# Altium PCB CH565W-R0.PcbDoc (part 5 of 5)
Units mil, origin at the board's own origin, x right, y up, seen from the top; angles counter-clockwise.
Board outline 3947.04 x 3947.04 mil, 4 copper layers (Top Layer, Layer 1, Layer 2, Bottom Layer), stack 23.756 mil thick; 204 components, 168 nets, 932 pads, 1005 vias.
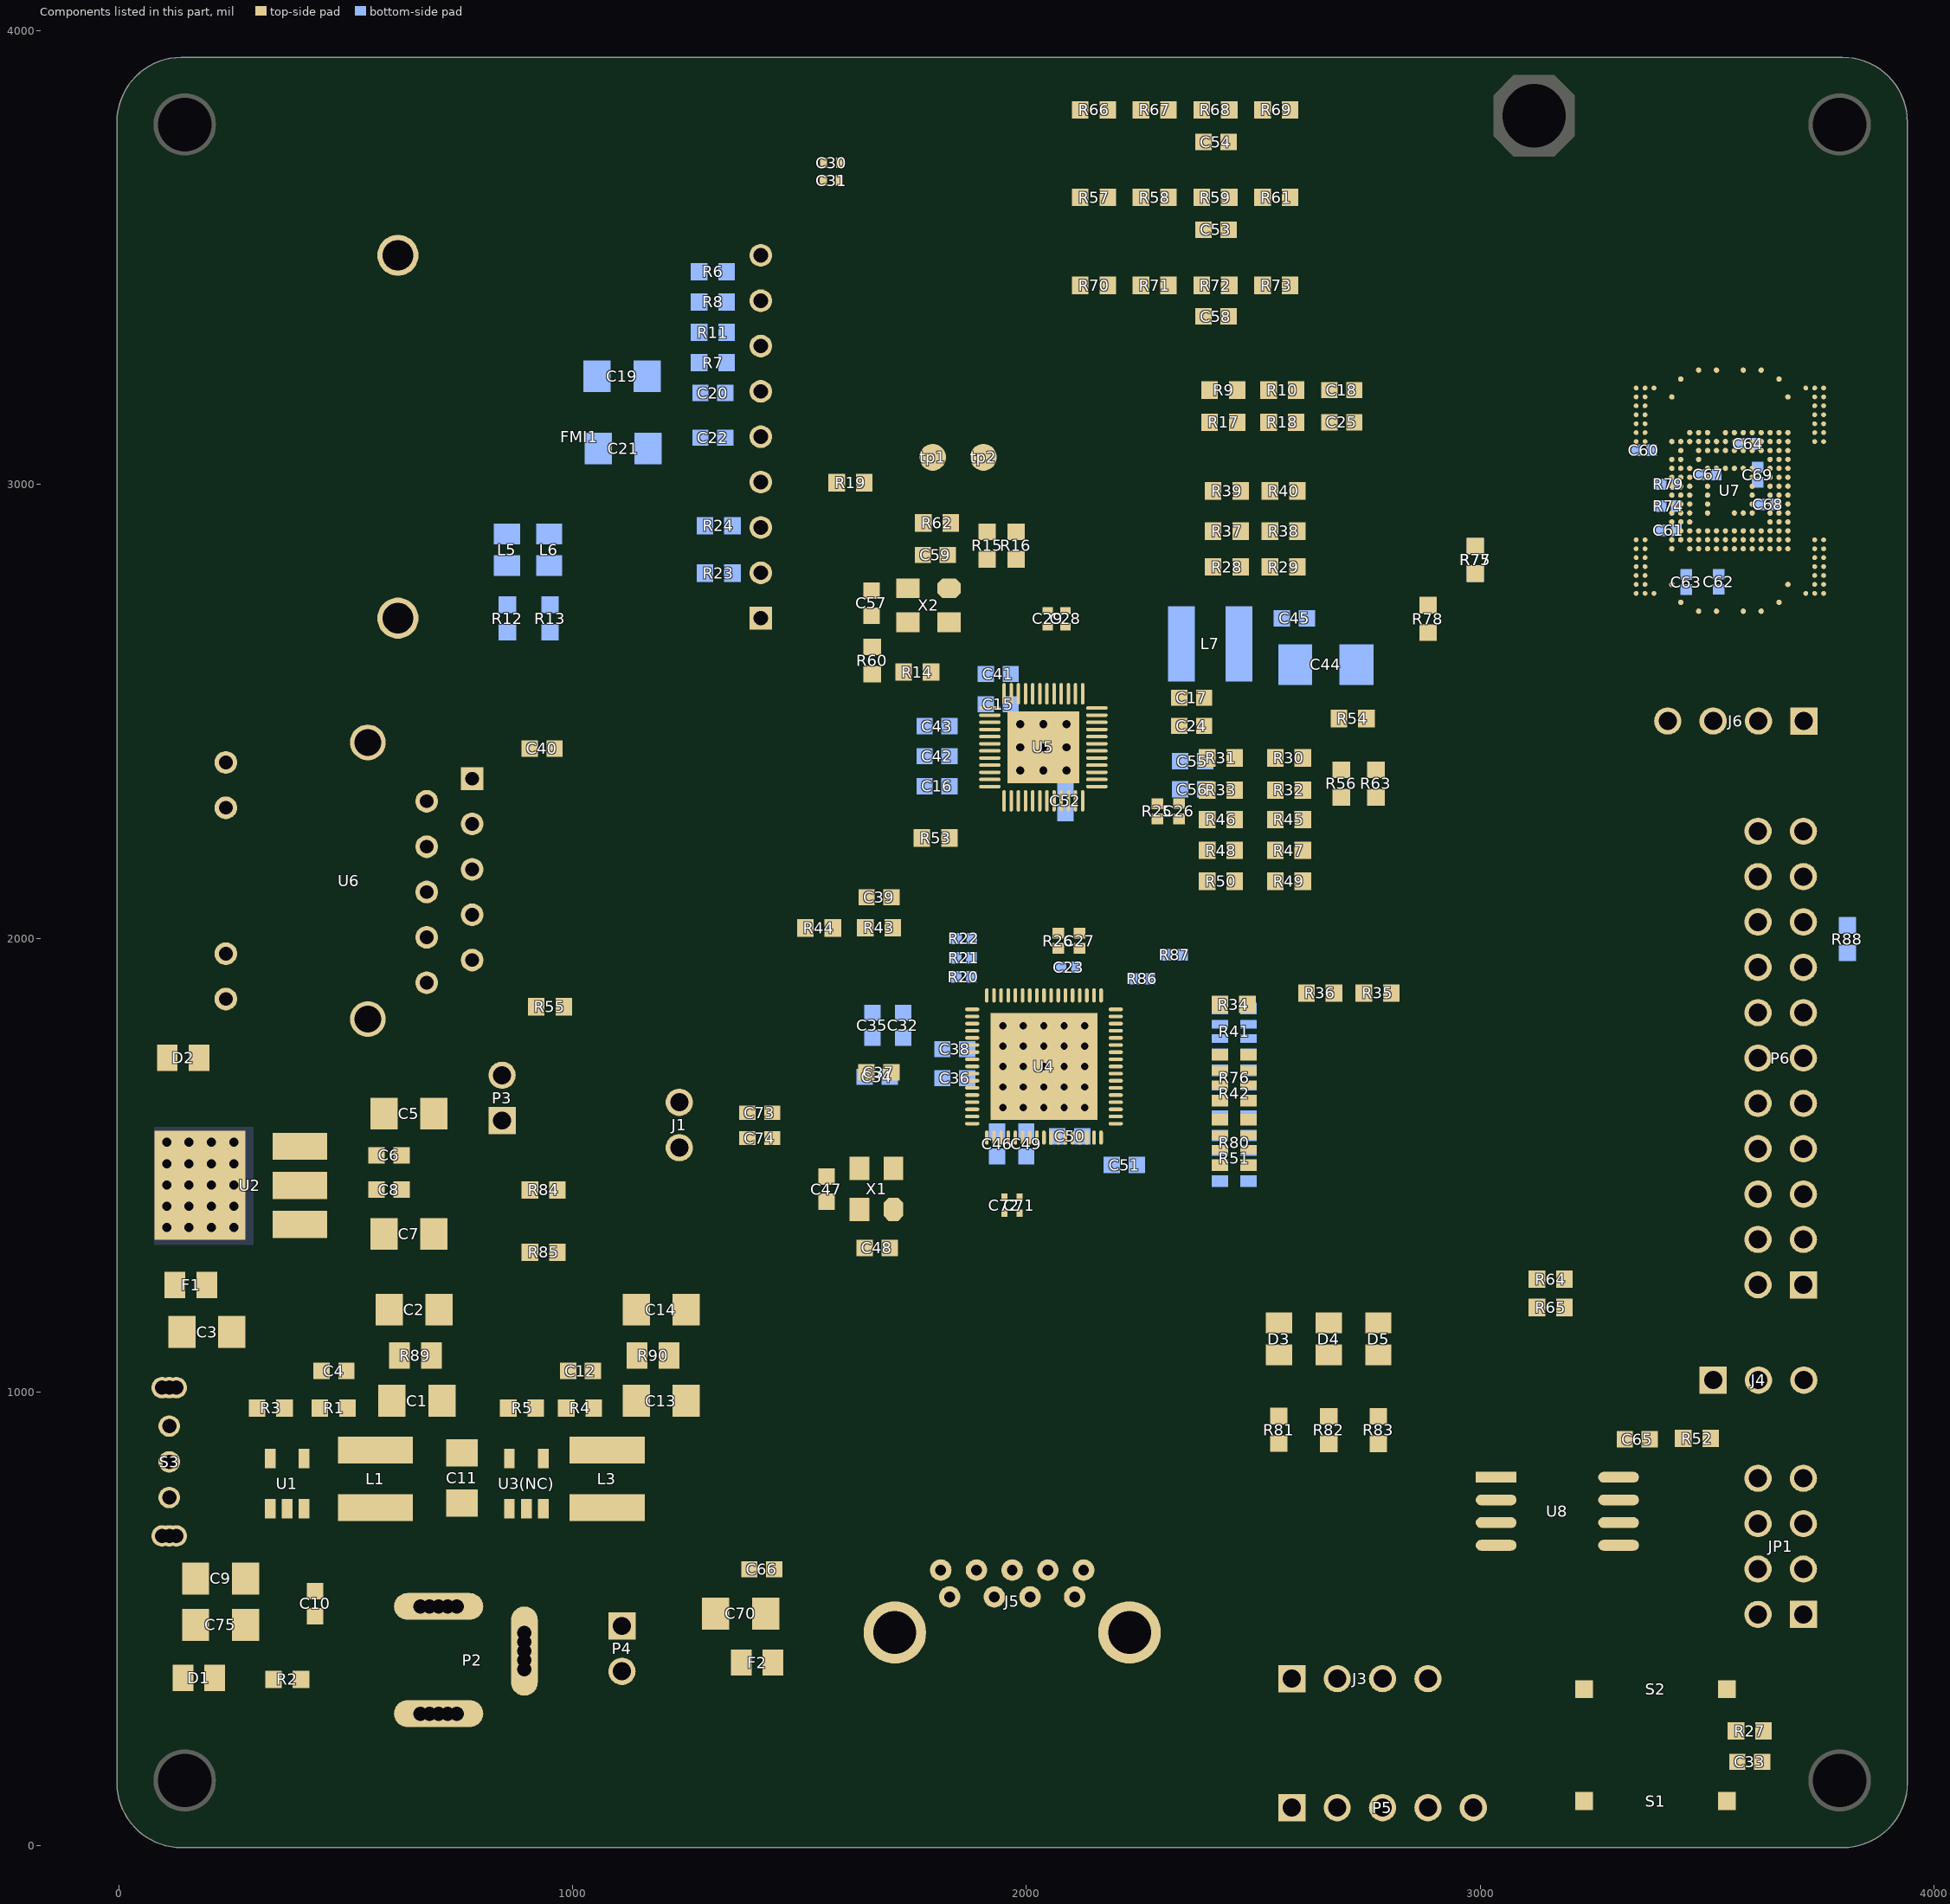
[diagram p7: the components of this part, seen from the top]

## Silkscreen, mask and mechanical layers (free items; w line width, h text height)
Top Overlay:
  circle w10: c144.36,3793.89 r118.11
  circle w10: c3792.65,3793.89 r118.11
  circle w10: c144.36,143.12 r118.11
  circle w10: c3792.65,143.12 r118.11
  region: 2564.33,2060.37 2535.29,2013.45 2594.57,2013.45
  lines w8: 2369.6,2069.8 2639.31,2069.8 ; 2566.18,2039.46 2566.18,1953.98 2685.29,1953.98 ; 2651.29,1953.98 2870.66,1953.98 2870.66,2209.92 2651.29,2209.92 2651.29,1953.98
  text "CH565W-R0-1v1" at 2960.49,3545.69 h50
  text "RXD3" at 3562.63,2546.69 h32
  text "TXD3" at 3430.15,2546.11 h32
  text "POW" at 3679.99,2546.11 h32
  text "GND" at 3332.85,2545.53 h32
  text "D10" at 3453.39,2217.34 h32
  text "D11" at 3774.84,2211.87 h32
  text "D8" at 3480.05,2116.98 h32
  text "D9" at 3774.84,2114.8 h32
  text "PWDN" at 3416.07,2016.63 h32
  text "CLK" at 3448.06,1916.27 h32
  text "D7" at 3774.84,1914.49 h32
  text "D6" at 3480.05,1815.91 h32
  text "D5" at 3774.84,1814.68 h32
  text "D4" at 3480.05,1715.55 h32
  text "D3" at 3774.84,1712.82 h32
  text "VIO" at 908.08,1680.61 h32
  text "D2" at 3480.05,1615.2 h32
  text "D1" at 3774.84,1615.06 h32
  text "3V3" at 909.83,1575.38 h32
  text "D0" at 3480.05,1514.84 h32
  text "RESET" at 3774.84,1510.46 h32
  text "SDA" at 3448.06,1414.48 h32
  text "HERF" at 3774.84,1413.56 h32
  text "SCL" at 3448.06,1314.12 h32
  text "SYNC" at 3774.84,1310.29 h32
  text "GND" at 3448.06,1213.77 h32
  text "5V" at 3480.73,1089.66 h32
  text "3V3" at 3672.88,1089.66 h32
  text "ON" at 202.61,971.97 h40 r270
  text "OFF" at 202.61,850.76 h40 r270
  text "RST" at 3453.38,792.21 h32
  text "MOSI" at 3774.98,787.86 h32
  text "GND" at 3453.38,689.99 h32
  text "MISO" at 3774.98,687.09 h32
  text "POW" at 3453.38,587.77 h32
  text "SCK" at 3774.98,586.32 h32
  text "3V3" at 3453.38,485.55 h32
  text "SCS" at 3774.98,485.55 h32
  text "POW" at 955.44,467.16 h32
  text "GND" at 2529.67,427.32 h32
  text "TXD" at 2636.43,427.32 h32
  text "RXD" at 2745.05,427.32 h32
  text "POW" at 2853.67,427.32 h32
  text "DOWNLOAD" at 3257.79,427.37 h32
  text "GND" at 951.61,362.9 h32
  text "RST" at 3256.4,178.71 h32
  text "GND" at 2524.59,147.57 h32
  text "RST" at 2634.14,147.57 h32
  text "TIO" at 2737.76,147.57 h32
  text "TCK" at 2839.67,147.57 h32
  text "3V3" at 2940.73,147.57 h32
Mechanical 1:
  lines w10: 0,137.56 ccw(c137.68,137.68) 137.8,0 3799.21,0 ; 0,137.8 0,3799.21 ; 0,3799.54 cw(c137.63,3799.38) 137.79,3937.01 ; 136.97,3937.01 3799.21,3937.01 ; 3799.5,0 ccw(c3799.36,137.65) 3937.01,137.8 3937.01,3799.21 ccw(c3799.21,3799.21) 3799.21,3937.01 ; 3799.21,3937.01 3799.21,3937.01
